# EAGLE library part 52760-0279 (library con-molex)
MOLEX Connector SD-52760-**79 Source: 52760-1079_sd molex.pdf
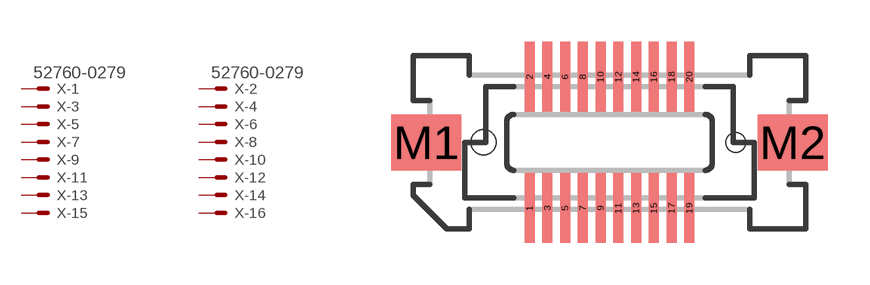
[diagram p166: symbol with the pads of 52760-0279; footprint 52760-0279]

Designator prefix X; gates -1=MV -2=MV -3=M -4=M -5=M -6=M -7=M -8=M -9=M -10=M -11=M -12=M -13=M -14=M -15=M -16=M -17=M -18=M -19=M -20=M

## 52760-0279 (MPN: 52760-0279; OC_FARNELL: unknown; OC_NEWARK: 92M6430)  [52760-0279]
1  -1:S  pas
2  -2:S  pas
3  -3:S  pas
4  -4:S  pas
5  -5:S  pas
6  -6:S  pas
7  -7:S  pas
8  -8:S  pas
9  -9:S  pas
10  -10:S  pas
11  -11:S  pas
12  -12:S  pas
13  -13:S  pas
14  -14:S  pas
15  -15:S  pas
16  -16:S  pas
17  -17:S  pas
18  -18:S  pas
19  -19:S  pas
20  -20:S  pas

## Footprint 52760-0279 (pad centres in mm)
MOLEX Connector SD-52760-**79 Source: 52760-1079_sd molex.pdf
smd 0.35 x 2.5: 1 -2.857,-2.35; 2 -2.857,2.35; 3 -2.223,-2.35; 4 -2.223,2.35; 5 -1.587,-2.35; 6 -1.587,2.35; 7 -0.953,-2.35; 8 -0.953,2.35; 9 -0.318,-2.35; 10 -0.318,2.35; 11 0.318,-2.35; 12 0.318,2.35; 13 0.953,-2.35; 14 0.953,2.35; 15 1.587,-2.35; 16 1.587,2.35; 17 2.223,-2.35; 18 2.223,2.35; 19 2.857,-2.35; 20 2.857,2.35
smd 2.5 x 2: M1 -6.55,0; M2 6.55,0
hole 0.9 at -4.51,0
hole 0.7 at 4.51,0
